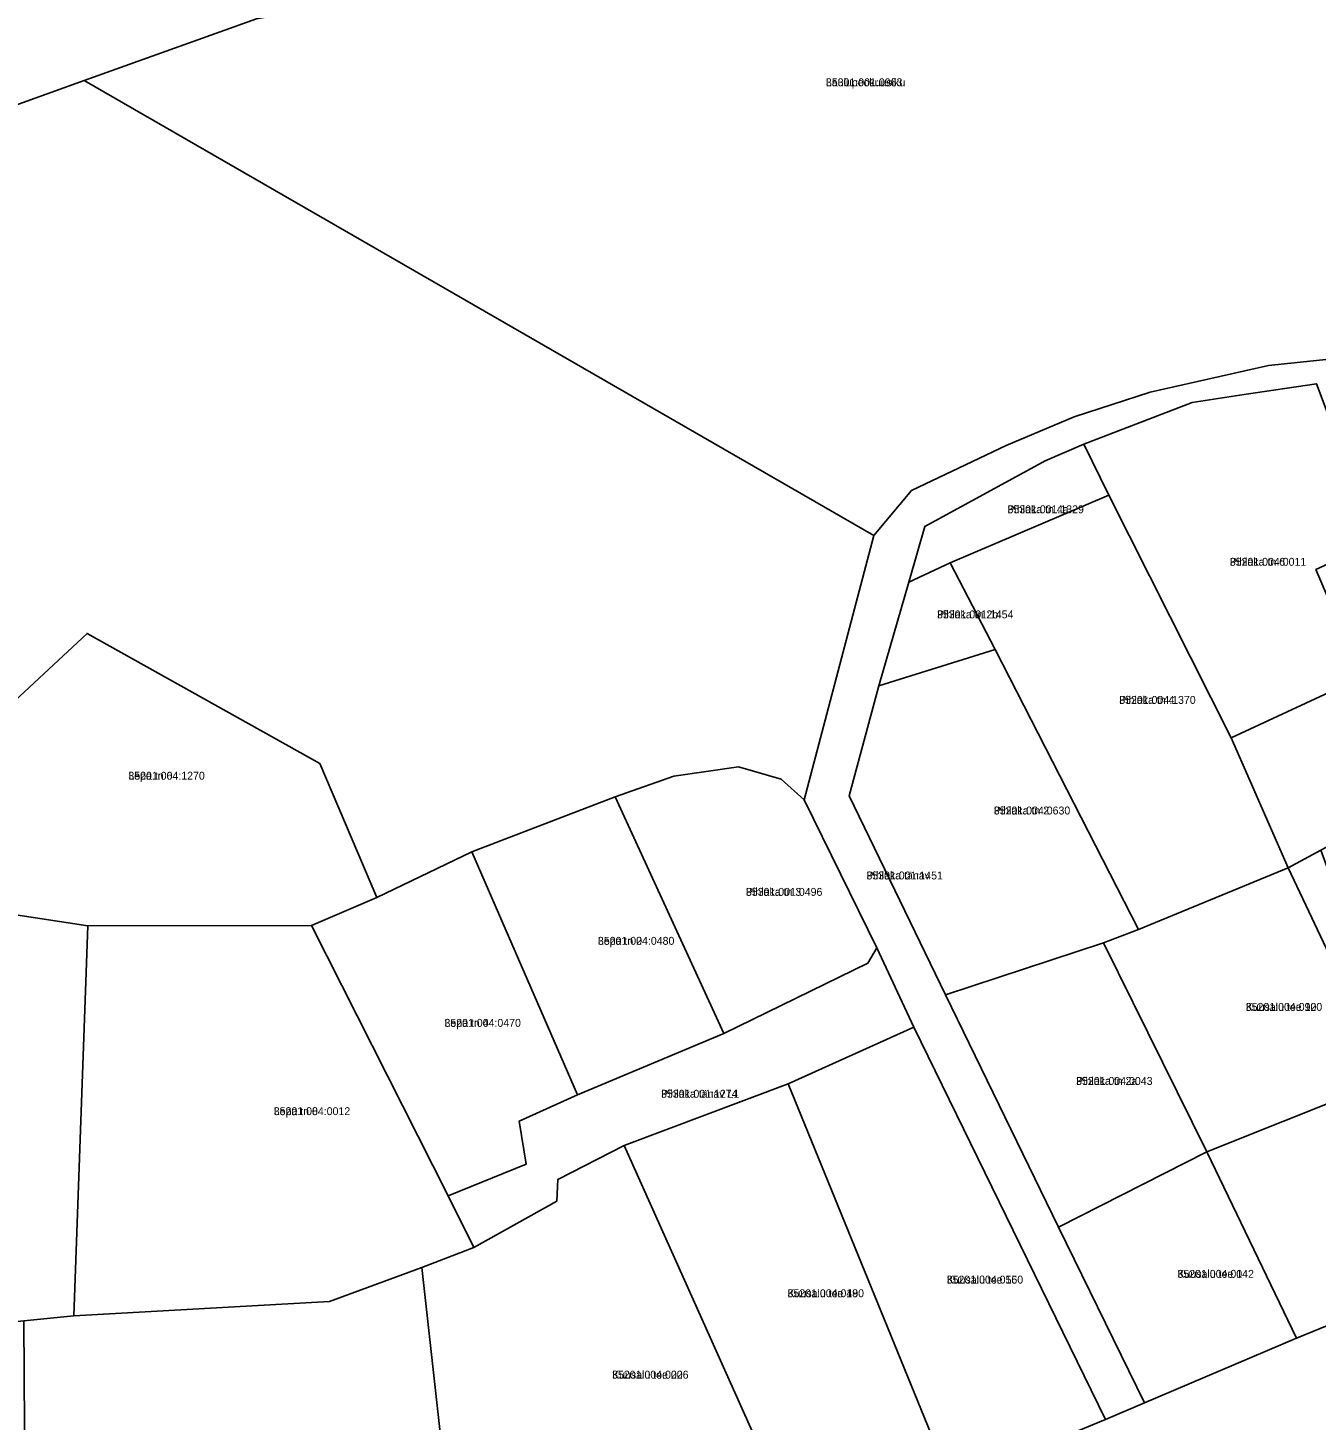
# Model space of a CAD drawing. Extents: x 570181 to 611446, y 6571894 to 6617855.
# Drawn here: x 581585 to 581829.4, y 6590685 to 6590949.1 of the extents above; entities that cross this region are included whole.
import ezdxf

# ---------------------------------------------------------------- set-up
doc = ezdxf.new("R2010")
doc.units = 0
for name, color, linetype in [('L_AADRESS', 7, 'Continuous'), ('PIIR', 7, 'Continuous'), ('TUNNUS', 7, 'Continuous')]:
    doc.layers.add(name, color=color, linetype=linetype)

msp = doc.modelspace()

# ---------------------------------------------------------------- linework, layer by layer
at = {"layer": 'PIIR'}
for points in [[(581560.52, 6591031.05), (581585.98, 6591026.42), (581686, 6591033.59), (581701.68, 6590963.86), (581628.38, 6590950.76), (581595.72, 6590939.1), (581498.44, 6590904.07)], [(581498.44, 6590904.07), (581595.72, 6590939.1), (581745.49, 6590852.75), (581732.32, 6590802.62), (581727.96, 6590806.56), (581719.82, 6590808.9), (581707.57, 6590807.11), (581696.43, 6590803.2), (581669.27, 6590792.75), (581651.24, 6590784.07), (581640.43, 6590809.51), (581596.27, 6590834.19), (581545.04, 6590786.54)], [(581829.49, 6590881.54), (581815.77, 6590879.49), (581805.88, 6590878.01), (581785.36, 6590870.08), (581777.99, 6590866.95), (581755.2, 6590854.5), (581752.13, 6590843.89), (581746.44, 6590824.26), (581740.83, 6590803.4), (581759.09, 6590765.62), (581780.51, 6590721.59), (581796.88, 6590688.26), (581789.43, 6590685.1), (581753.11, 6590759.48), (581746.08, 6590774.55), (581732.32, 6590802.62), (581745.49, 6590852.75), (581752.66, 6590861.31), (581770.63, 6590869.86), (581783.5, 6590875.26), (581797.92, 6590879.98), (581820.38, 6590884.99), (581833.1, 6590886.33)], [(581760.16, 6590673.03), (581789.43, 6590685.1), (581796.88, 6590688.26), (581825.71, 6590700.5), (581854.66, 6590712.34), (581863.18, 6590707.22), (581887.09, 6590714.45), (581909.24, 6590718.98), (581920.31, 6590719.98), (581928.39, 6590720.83), (581941.91, 6590718.29), (581967.14, 6590713.55), (581970.16, 6590712.87), (581981.74, 6590710.27), (581999.7, 6590706.24), (582047.77, 6590695.88), (582055.68, 6590693.78), (582092.03, 6590685.42), (582116.25, 6590689.31), (582170.94, 6590701.24), (582187.31, 6590705.49), (582202.51, 6590694.27), (582199.88, 6590678.46)]]:
    msp.add_lwpolyline(points, dxfattribs=at)
for points in [[(581745.49, 6590852.75), (581595.72, 6590939.1), (581628.38, 6590950.76), (581701.68, 6590963.86), (581840.84, 6590998.8), (581953.05, 6591023.21), (581857.25, 6590983.74), (581875.68, 6590936.71), (581899.88, 6590894.13), (581884.92, 6590889.95), (581869.62, 6590885.68), (581855, 6590881.3), (581850.56, 6590879.95), (581847.6, 6590880.18), (581833.1, 6590886.33), (581820.38, 6590884.99), (581797.92, 6590879.98), (581783.5, 6590875.26), (581770.63, 6590869.86), (581752.66, 6590861.31)], [(581840.71, 6590851.57), (581829.37, 6590846.31), (581838.08, 6590825.9), (581813.32, 6590814.41), (581790.06, 6590860.45), (581785.36, 6590870.08), (581805.88, 6590878.01), (581815.77, 6590879.49), (581829.49, 6590881.54)], [(581785.36, 6590870.08), (581790.06, 6590860.45), (581759.98, 6590847.57), (581752.13, 6590843.89), (581755.2, 6590854.5), (581777.99, 6590866.95)], [(581790.06, 6590860.45), (581813.32, 6590814.41), (581824.14, 6590789.71), (581795.7, 6590778.06), (581768.55, 6590831.13), (581759.98, 6590847.57)], [(581856.46, 6590858.97), (581870.35, 6590814.59), (581830.33, 6590793.08), (581824.14, 6590789.71), (581813.32, 6590814.41), (581838.08, 6590825.9), (581829.37, 6590846.31), (581840.71, 6590851.57)], [(581746.44, 6590824.26), (581752.13, 6590843.89), (581759.98, 6590847.57), (581768.55, 6590831.13)], [(581596.27, 6590834.19), (581640.43, 6590809.51), (581651.24, 6590784.07), (581638.84, 6590778.76), (581596.41, 6590778.71), (581545.04, 6590786.54)], [(581759.09, 6590765.62), (581740.83, 6590803.4), (581746.44, 6590824.26), (581768.55, 6590831.13), (581795.7, 6590778.06), (581789.06, 6590775.53)], [(581717.07, 6590758.31), (581696.43, 6590803.2), (581707.57, 6590807.11), (581719.82, 6590808.9), (581727.96, 6590806.56), (581732.32, 6590802.62), (581746.08, 6590774.55), (581744.35, 6590771.63)], [(581689.27, 6590746.68), (581669.27, 6590792.75), (581696.43, 6590803.2), (581717.07, 6590758.31)], [(581830.33, 6590793.08), (581842, 6590761.18), (581845.86, 6590750.62), (581843.07, 6590749.61), (581824.14, 6590789.71)], [(581638.84, 6590778.76), (581651.24, 6590784.07), (581669.27, 6590792.75), (581689.27, 6590746.68), (581678.23, 6590741.69), (581679.57, 6590733.54), (581664.74, 6590727.54)], [(581837.49, 6590747.35), (581808.66, 6590735.83), (581789.06, 6590775.53), (581795.7, 6590778.06), (581824.14, 6590789.71), (581843.07, 6590749.61)], [(581593.74, 6590704.77), (581584.28, 6590703.78), (581548.52, 6590700.24), (581543.41, 6590699.85), (581545.04, 6590786.54), (581596.41, 6590778.71)], [(581638.84, 6590778.76), (581664.74, 6590727.54), (581669.61, 6590717.7), (581659.76, 6590713.91), (581642.22, 6590707.47), (581593.74, 6590704.77), (581596.41, 6590778.71)], [(581759.09, 6590765.62), (581789.06, 6590775.53), (581808.66, 6590735.83), (581780.51, 6590721.59)], [(581744.35, 6590771.63), (581746.08, 6590774.55), (581753.11, 6590759.48), (581729.26, 6590748.76), (581698.13, 6590737.03), (581685.57, 6590730.62), (581685.4, 6590726.53), (581669.61, 6590717.7), (581664.74, 6590727.54), (581679.57, 6590733.54), (581678.23, 6590741.69), (581689.27, 6590746.68), (581717.07, 6590758.31)], [(581760.16, 6590673.03), (581729.26, 6590748.76), (581753.11, 6590759.48), (581789.43, 6590685.1)], [(581760.16, 6590673.03), (581731.95, 6590661.58), (581698.13, 6590737.03), (581729.26, 6590748.76)], [(581825.71, 6590700.5), (581808.66, 6590735.83), (581837.49, 6590747.35), (581854.66, 6590712.34)], [(581698.13, 6590737.03), (581731.95, 6590661.58), (581683.93, 6590645.93), (581667.62, 6590643.36), (581659.76, 6590713.91), (581669.61, 6590717.7), (581685.4, 6590726.53), (581685.57, 6590730.62)], [(581780.51, 6590721.59), (581808.66, 6590735.83), (581825.71, 6590700.5), (581796.88, 6590688.26)], [(581667.62, 6590643.36), (581641.22, 6590639.2), (581584.68, 6590633.25), (581584.28, 6590703.78), (581593.74, 6590704.77), (581642.22, 6590707.47), (581659.76, 6590713.91)]]:
    msp.add_lwpolyline(points, close=True, dxfattribs=at)

# ---------------------------------------------------------------- texts
at = {"layer": 'L_AADRESS'}
for s, p in [('Laulupeokuusiku', (581736.42, 6590937.98)), ('Pihlaka tn 4a', (581770.86, 6590856.99)), ('Pihlaka tn 6', (581813.04, 6590847.03)), ('Pihlaka tn 2b', (581757.49, 6590837.05)), ('Pihlaka tn 4', (581792.06, 6590820.83)), ('Lepa tn 6', (581604.09, 6590806.45)), ('Pihlaka tn 2', (581768.27, 6590799.85)), ('Pihlaka tänav', (581744.11, 6590787.53)), ('Pihlaka tn 3', (581721.25, 6590784.42)), ('Lepa tn 2', (581693.17, 6590775.13)), ('Kuusalu tee 12', (581816.07, 6590762.6)), ('Lepa tn 4', (581664.06, 6590759.57)), ('Pihlaka tn 2a', (581783.88, 6590748.55)), ('Pihlaka tänav L1', (581705.15, 6590746.12)), ('Lepa tn 8', (581631.68, 6590742.82)), ('Kuusalu tee 16', (581759.34, 6590710.87)), ('Kuusalu tee 14', (581803.11, 6590711.96)), ('Kuusalu tee 18', (581729.14, 6590708.28)), ('Kuusalu tee 20', (581695.86, 6590692.84))]:
    msp.add_text(s, height=1.5, dxfattribs=at).set_placement(p)
at = {"layer": 'TUNNUS'}
for s, p in [('35301:001:0963', (581736.42, 6590937.98)), ('35301:001:1329', (581770.86, 6590856.99)), ('35201:004:0011', (581813.04, 6590847.03)), ('35301:001:1454', (581757.49, 6590837.05)), ('35201:004:1370', (581792.06, 6590820.83)), ('35201:004:1270', (581604.09, 6590806.45)), ('35201:004:0630', (581768.27, 6590799.85)), ('35301:001:1451', (581744.11, 6590787.53)), ('35301:001:0496', (581721.25, 6590784.42)), ('35201:004:0480', (581693.17, 6590775.13)), ('35201:004:0900', (581816.07, 6590762.6)), ('35201:004:0470', (581664.06, 6590759.57)), ('35201:004:0043', (581783.88, 6590748.55)), ('35301:001:1274', (581705.15, 6590746.12)), ('35201:004:0012', (581631.68, 6590742.82)), ('35201:004:0550', (581759.34, 6590710.87)), ('35201:004:0042', (581803.11, 6590711.96)), ('35201:004:0490', (581729.14, 6590708.28)), ('35201:004:0026', (581695.86, 6590692.84))]:
    msp.add_text(s, height=1.5, dxfattribs=at).set_placement(p)

doc.saveas('drawing.dxf')
